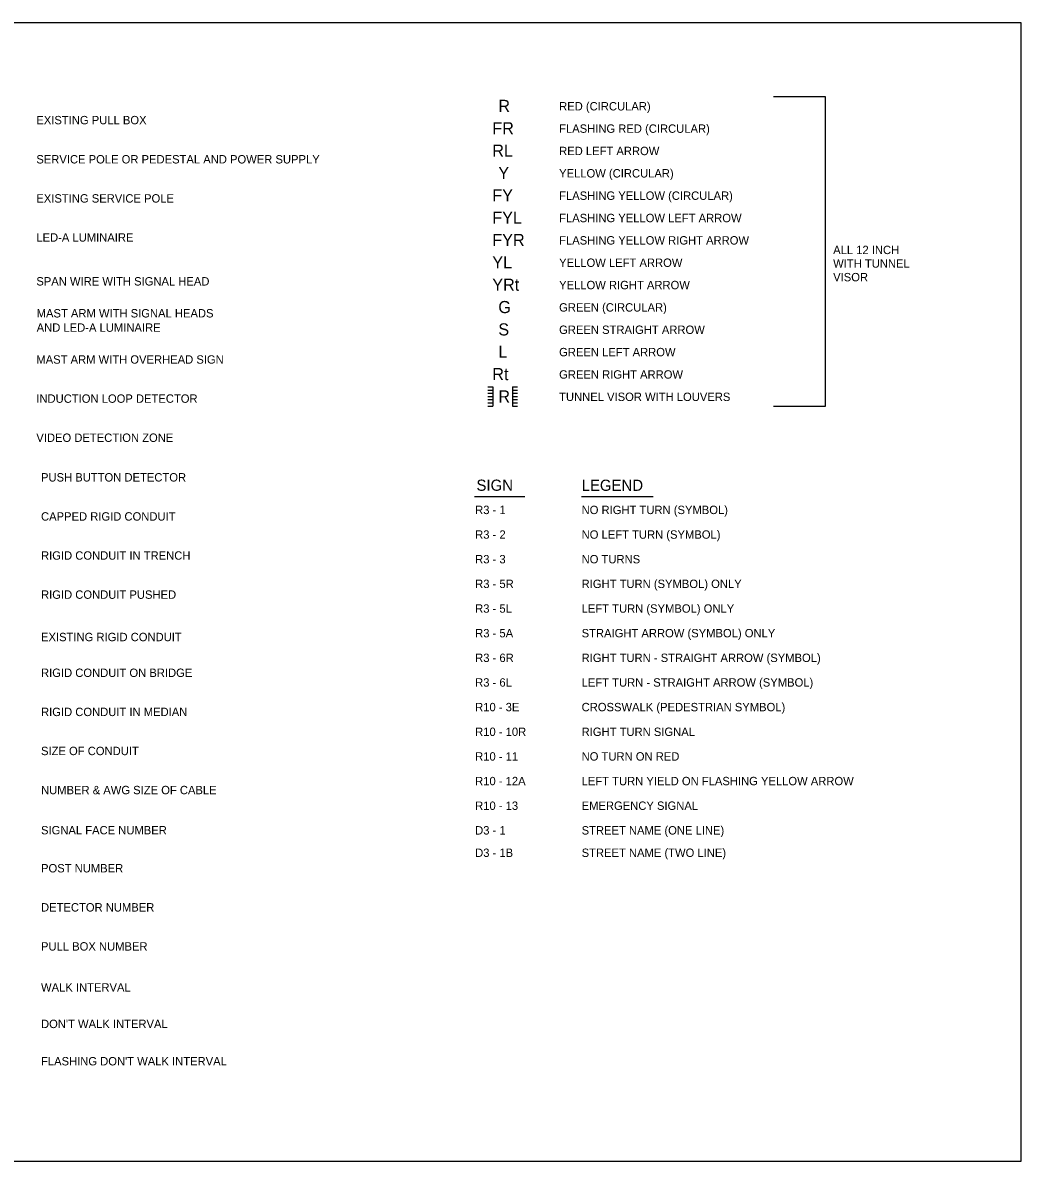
# Model space of a CAD drawing. Extents: x -439.1 to -407.9, y -458.1 to -437.7.
# Drawn here: x -425.73 to -407.86, y -458.05 to -437.68 of the extents above; entities that cross this region are included whole.
import ezdxf

# ---------------------------------------------------------------- set-up
doc = ezdxf.new("R2010")
doc.units = 0
doc.layers.add('Draft_Named_Boundary', color=7, linetype='Continuous')
doc.layers.add('Level 4', color=7, linetype='Continuous')

msp = doc.modelspace()

# ---------------------------------------------------------------- linework, layer by layer
at = {"layer": 'Draft_Named_Boundary'}
msp.add_lwpolyline([(-439.109, -458.051), (-407.859, -458.051), (-407.859, -437.676), (-439.109, -437.676)], close=True, dxfattribs=at)
at = {"layer": 'Level 4'}
for p, q in [((-412.293, -438.995), (-411.371, -438.995)), ((-411.371, -438.995), (-411.371, -444.545)), ((-417.408, -444.192), (-417.319, -444.192)), ((-417.408, -444.249), (-417.319, -444.249)), ((-417.408, -444.306), (-417.319, -444.306)), ((-417.408, -444.364), (-417.319, -444.364)), ((-417.319, -444.192), (-417.319, -444.535)), ((-416.962, -444.192), (-416.962, -444.535)), ((-416.962, -444.192), (-416.873, -444.192)), ((-416.962, -444.249), (-416.873, -444.249)), ((-416.962, -444.306), (-416.873, -444.306)), ((-416.962, -444.364), (-416.873, -444.364)), ((-417.408, -444.421), (-417.319, -444.421)), ((-417.408, -444.478), (-417.319, -444.478)), ((-417.408, -444.535), (-417.319, -444.535)), ((-416.962, -444.421), (-416.873, -444.421)), ((-416.962, -444.478), (-416.873, -444.478)), ((-416.962, -444.535), (-416.873, -444.535)), ((-411.371, -444.545), (-412.293, -444.545)), ((-417.646, -446.157), (-416.741, -446.157)), ((-415.73, -446.157), (-414.445, -446.157))]:
    msp.add_line(p, q, dxfattribs=at)

# ---------------------------------------------------------------- texts
for s, height, p in [('R', 0.217, (-417.218, -439.272)), ('RED (CIRCULAR)', 0.15, (-416.13, -439.245)), ('EXISTING PULL BOX', 0.15, (-425.487, -439.493)), ('FR', 0.2167, (-417.326, -439.672)), ('FLASHING RED (CIRCULAR)', 0.15, (-416.13, -439.645)), ('RL', 0.2167, (-417.326, -440.072)), ('RED LEFT ARROW', 0.15, (-416.13, -440.045)), ('SERVICE POLE OR PEDESTAL AND POWER SUPPLY', 0.15, (-425.487, -440.194)), ('Y', 0.217, (-417.218, -440.472)), ('YELLOW (CIRCULAR)', 0.15, (-416.13, -440.445)), ('FY', 0.2167, (-417.326, -440.872)), ('FY', 0.2167, (-417.326, -440.872)), ('FY', 0.2167, (-417.326, -440.872)), ('FLASHING YELLOW (CIRCULAR)', 0.15, (-416.13, -440.845)), ('EXISTING SERVICE POLE', 0.15, (-425.487, -440.894)), ('FYL', 0.2167, (-417.326, -441.272)), ('FLASHING YELLOW LEFT ARROW', 0.15, (-416.13, -441.245)), ('LED-A LUMINAIRE', 0.15, (-425.487, -441.593)), ('FYR', 0.2167, (-417.326, -441.672)), ('FLASHING YELLOW RIGHT ARROW', 0.15, (-416.13, -441.645)), ('ALL 12 INCH', 0.15, (-411.225, -441.816)), ('YL', 0.2167, (-417.326, -442.072)), ('YELLOW LEFT ARROW', 0.15, (-416.13, -442.045)), ('WITH TUNNEL', 0.15, (-411.225, -442.059)), ('SPAN WIRE WITH SIGNAL HEAD', 0.15, (-425.487, -442.378)), ('YRt', 0.2167, (-417.326, -442.472)), ('YELLOW RIGHT ARROW', 0.15, (-416.13, -442.445)), ('VISOR', 0.15, (-411.225, -442.303)), ('G', 0.217, (-417.218, -442.872)), ('GREEN (CIRCULAR)', 0.15, (-416.13, -442.845)), ('MAST ARM WITH SIGNAL HEADS', 0.15, (-425.481, -442.95)), ('AND LED-A LUMINAIRE', 0.15, (-425.481, -443.206)), ('S', 0.217, (-417.218, -443.272)), ('GREEN STRAIGHT ARROW', 0.15, (-416.13, -443.245)), ('L', 0.217, (-417.218, -443.672)), ('GREEN LEFT ARROW', 0.15, (-416.13, -443.645)), ('MAST ARM WITH OVERHEAD SIGN', 0.15, (-425.487, -443.777)), ('Rt', 0.2167, (-417.326, -444.072)), ('GREEN RIGHT ARROW', 0.15, (-416.13, -444.045)), ('INDUCTION LOOP DETECTOR', 0.15, (-425.487, -444.477)), ('R', 0.217, (-417.218, -444.472)), ('TUNNEL VISOR WITH LOUVERS', 0.15, (-416.13, -444.445)), ('VIDEO DETECTION ZONE', 0.15, (-425.487, -445.177)), ('PUSH BUTTON DETECTOR', 0.15, (-425.403, -445.886)), ('SIGN ', 0.2, (-417.609, -446.052)), ('LEGEND   ', 0.2, (-415.727, -446.053)), ('R3 - 1', 0.15, (-417.633, -446.469)), ('NO RIGHT TURN (SYMBOL)', 0.15, (-415.727, -446.469)), ('CAPPED RIGID CONDUIT', 0.15, (-425.403, -446.586)), ('R3 - 2', 0.15, (-417.633, -446.91)), ('NO LEFT TURN (SYMBOL)', 0.15, (-415.727, -446.91)), ('RIGID CONDUIT IN TRENCH', 0.15, (-425.403, -447.285)), ('R3 - 3', 0.15, (-417.633, -447.351)), ('NO TURNS', 0.15, (-415.727, -447.351)), ('RIGHT TURN (SYMBOL) ONLY', 0.15, (-415.727, -447.792)), ('RIGID CONDUIT PUSHED', 0.15, (-425.403, -447.985)), ('R3 - 5R', 0.15, (-417.633, -447.792)), ('R3 - 5L', 0.15, (-417.633, -448.234)), ('LEFT TURN (SYMBOL) ONLY', 0.15, (-415.727, -448.234)), ('EXISTING RIGID CONDUIT', 0.15, (-425.403, -448.744)), ('R3 - 5A', 0.15, (-417.633, -448.675)), ('STRAIGHT ARROW (SYMBOL) ONLY', 0.15, (-415.727, -448.675)), ('R3 - 6R', 0.15, (-417.633, -449.116)), ('RIGHT TURN - STRAIGHT ARROW (SYMBOL)', 0.15, (-415.727, -449.116)), ('RIGID CONDUIT ON BRIDGE', 0.15, (-425.403, -449.384)), ('R3 - 6L', 0.15, (-417.633, -449.557)), ('LEFT TURN - STRAIGHT ARROW (SYMBOL)', 0.15, (-415.727, -449.557)), ('R10 - 3E', 0.15, (-417.633, -449.998)), ('CROSSWALK (PEDESTRIAN SYMBOL)', 0.15, (-415.727, -449.998)), ('RIGID CONDUIT IN MEDIAN', 0.15, (-425.403, -450.084)), ('R10 - 10R', 0.15, (-417.633, -450.44)), ('RIGHT TURN SIGNAL', 0.15, (-415.727, -450.44)), ('SIZE OF CONDUIT', 0.15, (-425.403, -450.783)), ('R10 - 11', 0.15, (-417.633, -450.881)), ('NO TURN ON RED', 0.15, (-415.727, -450.881)), ('R10 - 12A', 0.15, (-417.633, -451.322)), ('LEFT TURN YIELD ON FLASHING YELLOW ARROW', 0.15, (-415.727, -451.322)), ('NUMBER & AWG SIZE OF CABLE', 0.15, (-425.403, -451.483)), ('R10 - 13', 0.15, (-417.633, -451.763)), ('EMERGENCY SIGNAL', 0.15, (-415.727, -451.763)), ('SIGNAL FACE NUMBER', 0.15, (-425.403, -452.201)), ('D3 - 1', 0.15, (-417.633, -452.204)), ('STREET NAME (ONE LINE)', 0.15, (-415.727, -452.204)), ('D3 - 1B', 0.15, (-417.633, -452.605)), ('STREET NAME (TWO LINE)', 0.15, (-415.727, -452.605)), ('POST NUMBER', 0.15, (-425.403, -452.882)), ('DETECTOR NUMBER', 0.15, (-425.403, -453.582)), ('PULL BOX NUMBER', 0.15, (-425.403, -454.281)), ('WALK INTERVAL', 0.15, (-425.403, -455.015)), ("DON'T WALK INTERVAL", 0.15, (-425.403, -455.668)), ("FLASHING DON'T WALK INTERVAL", 0.15, (-425.403, -456.336))]:
    msp.add_text(s, height=height, dxfattribs=at).set_placement(p)

doc.saveas('drawing.dxf')
